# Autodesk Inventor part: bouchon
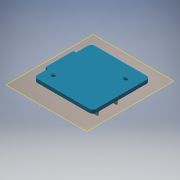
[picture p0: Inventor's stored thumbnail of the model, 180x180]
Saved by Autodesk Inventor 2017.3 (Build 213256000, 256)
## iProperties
Part Number: bouchon
Material: Plastique PMMA
Document SubType Name: Modeling
Designer: ficho
Density: 1.188 g/cm^3
Appearance: Turquoise
Mass: 15.4658 g
Surface Area: 74.7469 cm^2
Volume: 13.0183 cm^3
Author: ficho
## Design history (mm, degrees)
node "Plan de construction1"
sketch "Esquisse2"
  geometry: L1 (-40.15, -6)-(5, -6); L2 (8, -3)-(8, 40.9); L3 (5, 43.9)-(-40.15, 43.9); L4 (-43.161, 40.9)-(-43.15, -3); A1 r 3 centre (5, -3) between (5, -6) and (8, -3); A2 r 3 centre (5, 40.9) between (8, 40.9) and (5, 43.9); A3 r 3.011 centre (-40.15, 40.889) between (-40.15, 43.9) and (-43.161, 40.9); A4 r 3.001 centre (-40.149, -2.999) between (-43.15, -3) and (-40.15, -6); 1 further point
  constraints: 8 end point, 8 point on circle, 6 tangent, 4 centre point, 2 perpendicular, 1 horizontal, 8 other
extrude "Extrusion1" new body sketch "Esquisse2" distance "d6" = 3; taper "d7" = 0 deg
sketch "Esquisse4"
  geometry: L1 (36, 0)-(0, 0) reference; L2 (-3, 3)-(-3, 34.9) reference; L3 (0, 37.9)-(40.15, 37.9) reference; L4 (40.15, 0)-(36, 0) reference; L5 (40.15, 0)-(40.15, 37.9); A1 r 3 centre (0, 3) between (-3, 3) and (0, 0) reference; A2 r 3 centre (0, 34.9) between (0, 37.9) and (-3, 34.9) reference; 1 further point
  constraints: 2 end point, 1 vertical
extrude "Extrusion3" join sketch "Esquisse4" distance "d13" = 3; taper "d14" = 0 deg
sketch "Esquisse5"
  geometry: C1 r 0.755 at (-2, 32.9) reference; C2 r 0.755 at (-36, 4) reference; 1 further point
hole "Perçage1" sketch "Esquisse5" at (-2, 32.9), (-36, 4) diameter "d15" = 2.5; stored, may be unused: countersink angle "d19" = 90 deg, drill point angle "d21" = 118 deg; dims "d16" = 6, "d17" = 4, "d18" = 2, "d20" = 8
sketch "Esquisse6"
  geometry: C1 r 4 at (2, 32.9) reference; C2 r 4 at (36, 4) reference; 1 further point
extrude "Extrusion4" cut sketch "Esquisse6" distance "d22" = 3; taper "d23" = 0 deg
sketch "Esquisse7"
  geometry: L1 (-43.161, 6.601)-(-46.161, 6.601); L2 (-46.161, 6.601)-(-46.161, 31.299); L3 (-46.161, 31.299)-(-43.161, 31.299); L4 (-43.161, 31.299)-(-43.161, 6.601); A1 r 8 centre (-50, 2.45) between (-43.161, 6.601) and (-50, 10.45) reference; A2 r 8 centre (-50, 35.45) between (-50, 27.45) and (-43.161, 31.299) reference; 1 further point
  constraints: 8 end point, 2 parallel, 1 horizontal, 1 perpendicular
  dimensions: "d24" = 3 distance of L2.end L3.end
extrude "Extrusion5" join sketch "Esquisse7" distance "d25" = 5; taper "d26" = 0 deg
fillet "Congé3" dims "d27" = 1
sketch "Esquisse8"
  geometry: L1 (10.6, 22.4)-(9.1, 22.4) reference; L2 (9.1, 21.337)-(3, 21.337); L3 (3, 31.9)-(3, 0) reference; L4 (9.1, 21.337)-(9.1, 22.4); L5 (10.6, 22.4)-(10.6, 21.9); L6 (10.6, 21.9)-(13.558, 22.4); L7 (13.558, 22.4)-(13.558, 23.275); L8 (13.558, 23.275)-(3, 23.275); L9 (3, 21.337)-(3, 23.275); L10 (10.6, 6.7)-(10.6, 22.4) reference; L11 (10.6, 14.55)-(6.256, 14.55); L12 (10.6, 6.7)-(9.1, 6.7); L13 (9.1, 7.763)-(3, 7.763); L14 (9.1, 7.763)-(9.1, 6.7); L15 (10.6, 6.7)-(10.6, 7.2); L16 (10.6, 7.2)-(13.558, 6.7); L17 (13.558, 6.7)-(13.558, 5.825); L18 (13.558, 5.825)-(3, 5.825); L19 (3, 7.763)-(3, 5.825); 1 further point
  constraints: 36 end point, 7 symmetric about line, 3 horizontal, 2 parallel, 2 perpendicular, 2 point on line, 1 collinear, 1 midpoint, 1 vertical, 3 other
  dimensions: "d28" = 0.5 distance of L1.start L5.end; "d29" = 3 distance of L5.end L6.end
extrude "Extrusion6" join sketch "Esquisse8" distance "d30" = 40; taper "d31" = 0 deg
sketch "Esquisse9"
  geometry: L1 (0, 0)-(-40, 0) reference; L2 (-33.239, 0)-(-13.239, 0); L3 (-13.239, 0)-(-13.239, 13.834); L4 (-13.239, 13.834)-(-33.239, 13.834); L5 (-33.239, 13.834)-(-33.239, 0); L6 (-5.738, 0)-(7.369, 0); L7 (7.369, 0)-(7.369, 13.834); L8 (7.369, 13.834)-(-5.738, 13.834); L9 (-5.738, 13.834)-(-5.738, 0); 1 further point
  constraints: 16 end point, 4 parallel, 3 point on line, 2 horizontal, 2 perpendicular
  dimensions: "d32" = 20 distance of L4.end L3.end; "d33" = 7.50046 distance between parallel lines of L9 L3
extrude "Extrusion7" cut sketch "Esquisse9" stored distance "d34" = 40; taper "d35" = 0 deg
node "Solide1"
node "Référence16"
node "Référence17"
node "Référence18"
node "Référence19"
node "Référence20"
node "Référence21"
node "Référence22"
node "Référence23"
node "Référence24"
node "Référence26"
node "Référence27"
node "Référence28"
